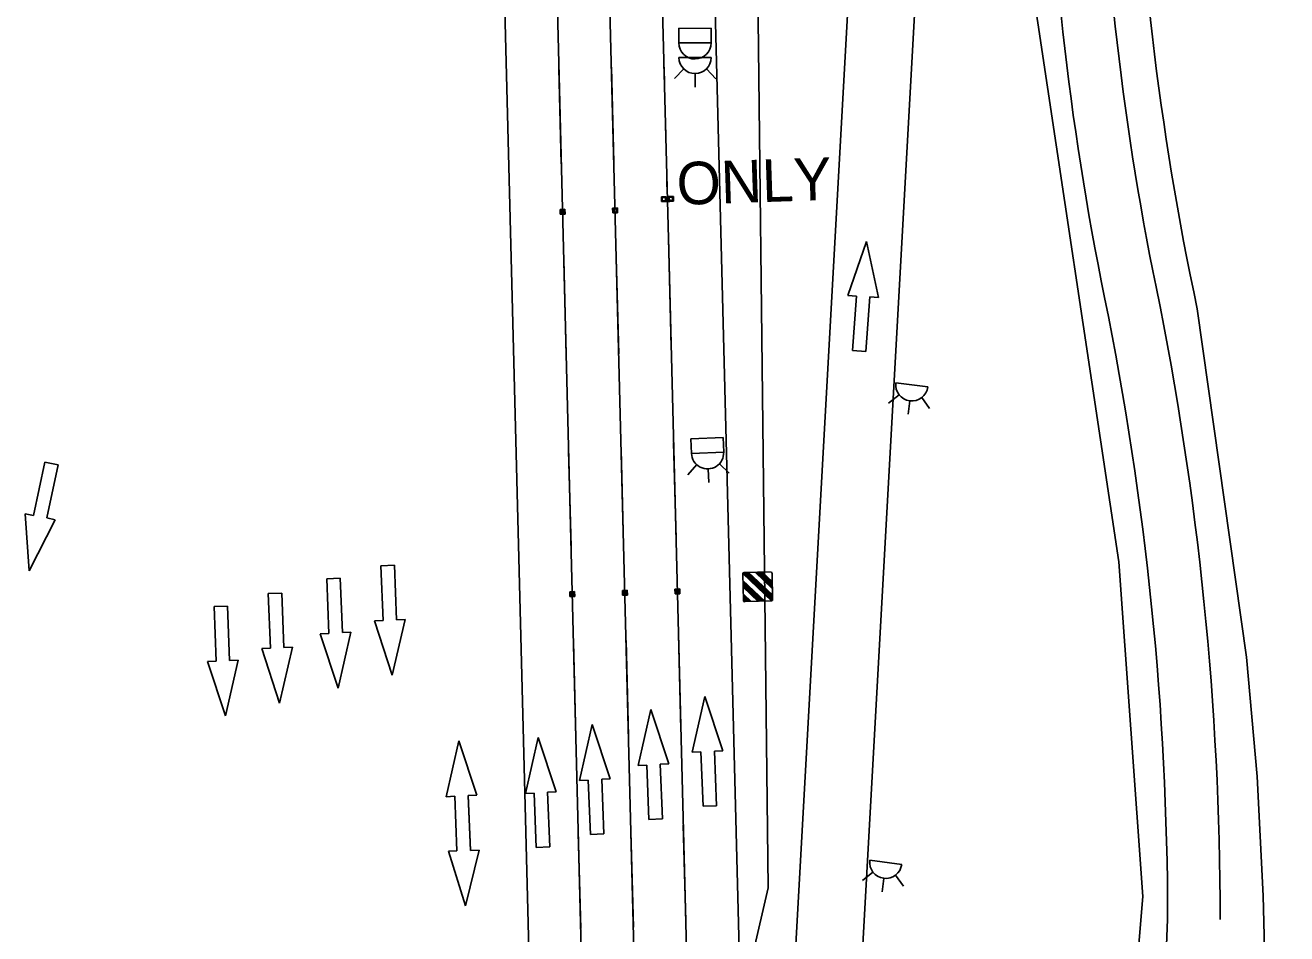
# Model space of a CAD drawing. Extents: x 2471014 to 2497726, y 6959577 to 6980268.
# Drawn here: x 2488453.1 to 2488716.9, y 6961822 to 6962012 of the extents above; entities that cross this region are included whole.
import ezdxf

# ---------------------------------------------------------------- set-up
doc = ezdxf.new("R2010")
doc.units = 0
for name, color, linetype in [('13', 7, 'Continuous'), ('18', 7, 'Continuous'), ('23', 7, 'Continuous'), ('59', 7, 'Continuous'), ('ALIGN_ML_IH35_NB_SB', 7, 'Continuous'), ('C-COMM-STRC', 7, 'Continuous'), ('Level 30', 7, 'Continuous'), ('Level 40', 7, 'Continuous'), ('p_structure fence', 7, 'Continuous'), ('RDW_EOT_35_CD', 7, 'Continuous'), ('RDWY_ALIGN_GP', 7, 'Continuous'), ('RDWY_PAVE_XSTREET_FOC', 7, 'Continuous'), ('S-BRDG-DECK', 7, 'Continuous'), ('V7_25', 7, 'Continuous'), ('V7_50', 7, 'Continuous')]:
    doc.layers.add(name, color=color, linetype=linetype)

msp = doc.modelspace()

# ---------------------------------------------------------------- linework, layer by layer
at = {"layer": '13'}
for p, q in [((2488544.08, 6962379.72), (2488575.08, 6961163.02)), ((2488613.41, 6961804.76), (2488630.42, 6962111.35)), ((2488683.27, 6961604.88), (2488692.01, 6961824.92))]:
    msp.add_line(p, q, dxfattribs=at)
for centre, radius, start, end in [((2489283.89, 6962078.36), 617.5, 181.08448, 191.51692), ((2488036.8, 6961824.25), 655.22, 0.05892, 11.51692)]:
    msp.add_arc(centre, radius, start, end, dxfattribs=at)
at = {"layer": '18'}
for p, q in [((2488588.07, 6962380.84), (2488602.73, 6961805.44)), ((2488616.31, 6961604.28), (2488644.4, 6962110.57))]:
    msp.add_line(p, q, dxfattribs=at)
msp.add_lwpolyline([(2488712.7, 6961791.89), (2488712.61, 6961804.88), (2488712.01, 6961829.87), (2488710.72, 6961854.85), (2488708.49, 6961879.81), (2488698.22, 6961952.71)], dxfattribs=at)
msp.add_arc((2489283.89, 6962078.36), 599, 181.08448, 192.10829, dxfattribs=at)
at = {"layer": '23'}
for p, q in [((2488587.14, 6961976.14), (2488586.13, 6961976.12)), ((2488586.15, 6961975.1), (2488586.13, 6961976.12)), ((2488586.13, 6961976.12), (2488586.29, 6961975.95)), ((2488586.31, 6961975.27), (2488586.15, 6961975.1)), ((2488586.15, 6961975.1), (2488586.42, 6961975.11)), ((2488586.29, 6961975.95), (2488586.43, 6961975.95)), ((2488586.99, 6961975.29), (2488586.31, 6961975.27)), ((2488586.42, 6961975.11), (2488587.17, 6961975.13)), ((2488586.43, 6961975.95), (2488586.97, 6961975.97)), ((2488586.97, 6961975.97), (2488587.14, 6961976.14)), ((2488587.17, 6961975.13), (2488586.99, 6961975.29)), ((2488587.14, 6961976.14), (2488587.17, 6961975.13)), ((2488588.64, 6961976.18), (2488587.63, 6961976.15)), ((2488587.65, 6961975.14), (2488587.63, 6961976.15)), ((2488587.63, 6961976.15), (2488587.79, 6961975.99)), ((2488587.81, 6961975.31), (2488587.65, 6961975.14)), ((2488587.65, 6961975.14), (2488587.92, 6961975.15)), ((2488587.79, 6961975.99), (2488587.93, 6961975.99)), ((2488588.49, 6961975.33), (2488587.81, 6961975.31)), ((2488587.92, 6961975.15), (2488588.67, 6961975.17)), ((2488587.93, 6961975.99), (2488588.47, 6961976.01)), ((2488588.47, 6961976.01), (2488588.64, 6961976.18)), ((2488588.67, 6961975.17), (2488588.49, 6961975.33)), ((2488588.64, 6961976.18), (2488588.67, 6961975.17)), ((2488565.95, 6961973.5), (2488564.94, 6961973.47)), ((2488564.96, 6961972.46), (2488564.94, 6961973.47)), ((2488564.94, 6961973.47), (2488565.1, 6961973.31)), ((2488565.12, 6961972.63), (2488564.96, 6961972.46)), ((2488564.96, 6961972.46), (2488565.23, 6961972.47)), ((2488565.1, 6961973.31), (2488565.24, 6961973.31)), ((2488565.8, 6961972.65), (2488565.12, 6961972.63)), ((2488565.23, 6961972.47), (2488565.98, 6961972.48)), ((2488565.24, 6961973.31), (2488565.78, 6961973.32)), ((2488565.78, 6961973.32), (2488565.95, 6961973.5)), ((2488565.98, 6961972.48), (2488565.8, 6961972.65)), ((2488565.95, 6961973.5), (2488565.98, 6961972.48)), ((2488576.95, 6961973.78), (2488575.93, 6961973.75)), ((2488575.96, 6961972.74), (2488575.93, 6961973.75)), ((2488575.93, 6961973.75), (2488576.1, 6961973.59)), ((2488576.12, 6961972.91), (2488575.96, 6961972.74)), ((2488575.96, 6961972.74), (2488576.23, 6961972.75)), ((2488576.1, 6961973.59), (2488576.24, 6961973.59)), ((2488576.79, 6961972.93), (2488576.12, 6961972.91)), ((2488576.23, 6961972.75), (2488576.97, 6961972.76)), ((2488576.24, 6961973.59), (2488576.78, 6961973.6)), ((2488576.78, 6961973.6), (2488576.95, 6961973.78)), ((2488576.97, 6961972.76), (2488576.79, 6961972.93)), ((2488576.95, 6961973.78), (2488576.97, 6961972.76)), ((2488567.99, 6961893.52), (2488566.98, 6961893.5)), ((2488567, 6961892.48), (2488566.98, 6961893.5)), ((2488566.98, 6961893.5), (2488567.14, 6961893.33)), ((2488567.16, 6961892.66), (2488567, 6961892.48)), ((2488567, 6961892.48), (2488567.27, 6961892.49)), ((2488567.14, 6961893.33), (2488567.28, 6961893.34)), ((2488567.83, 6961892.67), (2488567.16, 6961892.66)), ((2488567.27, 6961892.49), (2488568.02, 6961892.51)), ((2488567.28, 6961893.34), (2488567.82, 6961893.35)), ((2488567.82, 6961893.35), (2488567.99, 6961893.52)), ((2488568.02, 6961892.51), (2488567.83, 6961892.67)), ((2488567.99, 6961893.52), (2488568.02, 6961892.51)), ((2488578.99, 6961893.8), (2488577.97, 6961893.78)), ((2488578, 6961892.76), (2488577.97, 6961893.78)), ((2488577.97, 6961893.78), (2488578.14, 6961893.61)), ((2488578.15, 6961892.94), (2488578, 6961892.76)), ((2488578, 6961892.76), (2488578.27, 6961892.77)), ((2488578.14, 6961893.61), (2488578.28, 6961893.62)), ((2488578.83, 6961892.95), (2488578.15, 6961892.94)), ((2488578.27, 6961892.77), (2488579.01, 6961892.79)), ((2488578.28, 6961893.62), (2488578.81, 6961893.63)), ((2488578.81, 6961893.63), (2488578.99, 6961893.8)), ((2488579.01, 6961892.79), (2488578.83, 6961892.95)), ((2488578.99, 6961893.8), (2488579.01, 6961892.79)), ((2488589.98, 6961894.08), (2488588.97, 6961894.06)), ((2488588.99, 6961893.05), (2488588.97, 6961894.06)), ((2488588.97, 6961894.06), (2488589.13, 6961893.89)), ((2488589.15, 6961893.22), (2488588.99, 6961893.05)), ((2488588.99, 6961893.05), (2488589.26, 6961893.05)), ((2488589.13, 6961893.89), (2488589.27, 6961893.9)), ((2488589.83, 6961893.23), (2488589.15, 6961893.22)), ((2488589.26, 6961893.05), (2488590.01, 6961893.07)), ((2488589.27, 6961893.9), (2488589.81, 6961893.91)), ((2488589.81, 6961893.91), (2488589.98, 6961894.08)), ((2488590.01, 6961893.07), (2488589.83, 6961893.23)), ((2488589.98, 6961894.08), (2488590.01, 6961893.07))]:
    msp.add_line(p, q, dxfattribs=at)
for points in [[(2488586.31, 6961975.27), (2488586.29, 6961975.95), (2488586.97, 6961975.97), (2488586.99, 6961975.29)], [(2488587.81, 6961975.31), (2488587.79, 6961975.99), (2488588.47, 6961976.01), (2488588.49, 6961975.33)], [(2488565.12, 6961972.63), (2488565.1, 6961973.31), (2488565.78, 6961973.32), (2488565.8, 6961972.65)], [(2488576.12, 6961972.91), (2488576.1, 6961973.59), (2488576.78, 6961973.6), (2488576.79, 6961972.93)], [(2488567.16, 6961892.66), (2488567.14, 6961893.33), (2488567.82, 6961893.35), (2488567.83, 6961892.67)], [(2488578.15, 6961892.94), (2488578.14, 6961893.61), (2488578.81, 6961893.63), (2488578.83, 6961892.95)], [(2488589.15, 6961893.22), (2488589.13, 6961893.89), (2488589.81, 6961893.91), (2488589.83, 6961893.23)]]:
    msp.add_lwpolyline(points, close=True, dxfattribs=at)
at = {"layer": '59'}
msp.add_line((2488587.67, 6961964.64), (2488577.07, 6962380.56), dxfattribs=at)
at = {"layer": 'ALIGN_ML_IH35_NB_SB'}
for p, q in [((2488625.13, 6961955.46), (2488629.06, 6961966.79)), ((2488629.06, 6961966.79), (2488631.54, 6961955.07)), ((2488626.92, 6961955.33), (2488625.13, 6961955.46)), ((2488626.12, 6961943.99), (2488626.92, 6961955.33)), ((2488629.74, 6961955.19), (2488628.93, 6961943.79)), ((2488631.54, 6961955.07), (2488629.74, 6961955.19)), ((2488628.93, 6961943.79), (2488626.12, 6961943.99)), ((2488454.83, 6961909.46), (2488457.2, 6961920.64)), ((2488457.2, 6961920.64), (2488459.96, 6961920.05)), ((2488459.96, 6961920.05), (2488457.6, 6961908.93)), ((2488453.91, 6961897.88), (2488453.07, 6961909.83)), ((2488453.07, 6961909.83), (2488454.83, 6961909.46)), ((2488459.36, 6961908.56), (2488453.91, 6961897.88)), ((2488457.6, 6961908.93), (2488459.36, 6961908.56)), ((2488527.48, 6961898.92), (2488530.3, 6961899.03)), ((2488527.91, 6961887.5), (2488527.48, 6961898.92)), ((2488530.3, 6961899.03), (2488530.73, 6961887.66)), ((2488516.16, 6961896.21), (2488518.97, 6961896.31)), ((2488516.59, 6961884.79), (2488516.16, 6961896.21)), ((2488518.97, 6961896.31), (2488519.4, 6961884.95)), ((2488503.91, 6961893.11), (2488506.73, 6961893.21)), ((2488504.34, 6961881.68), (2488503.91, 6961893.11)), ((2488506.73, 6961893.21), (2488507.15, 6961881.85)), ((2488492.58, 6961890.39), (2488495.4, 6961890.5)), ((2488493.01, 6961878.97), (2488492.58, 6961890.39)), ((2488495.4, 6961890.5), (2488495.83, 6961879.14)), ((2488526.12, 6961887.43), (2488527.91, 6961887.5)), ((2488529.85, 6961876.04), (2488526.12, 6961887.43)), ((2488532.53, 6961887.73), (2488529.85, 6961876.04)), ((2488530.73, 6961887.66), (2488532.53, 6961887.73)), ((2488514.79, 6961884.72), (2488516.59, 6961884.79)), ((2488518.52, 6961873.33), (2488514.79, 6961884.72)), ((2488521.2, 6961885.02), (2488518.52, 6961873.33)), ((2488519.4, 6961884.95), (2488521.2, 6961885.02)), ((2488502.54, 6961881.62), (2488504.34, 6961881.68)), ((2488506.27, 6961870.23), (2488502.54, 6961881.62)), ((2488508.95, 6961881.92), (2488506.27, 6961870.23)), ((2488507.15, 6961881.85), (2488508.95, 6961881.92)), ((2488491.21, 6961878.91), (2488493.01, 6961878.97)), ((2488494.94, 6961867.52), (2488491.21, 6961878.91)), ((2488497.62, 6961879.21), (2488494.94, 6961867.52)), ((2488495.83, 6961879.14), (2488497.62, 6961879.21)), ((2488592.59, 6961859.92), (2488595.24, 6961871.62)), ((2488595.24, 6961871.62), (2488599.01, 6961860.24)), ((2488581.27, 6961857.18), (2488583.92, 6961868.87)), ((2488583.92, 6961868.87), (2488587.68, 6961857.5)), ((2488569.03, 6961854.04), (2488571.68, 6961865.74)), ((2488571.68, 6961865.74), (2488575.44, 6961854.36)), ((2488541.12, 6961850.63), (2488543.77, 6961862.33)), ((2488543.77, 6961862.33), (2488547.54, 6961850.95)), ((2488557.71, 6961851.3), (2488560.36, 6961863)), ((2488560.36, 6961863), (2488564.12, 6961851.62)), ((2488594.39, 6961859.99), (2488592.59, 6961859.92)), ((2488594.85, 6961848.63), (2488594.39, 6961859.99)), ((2488599.01, 6961860.24), (2488597.21, 6961860.17)), ((2488597.21, 6961860.17), (2488597.67, 6961848.75)), ((2488583.07, 6961857.25), (2488581.27, 6961857.18)), ((2488583.53, 6961845.89), (2488583.07, 6961857.25)), ((2488587.68, 6961857.5), (2488585.89, 6961857.42)), ((2488585.89, 6961857.42), (2488586.35, 6961846)), ((2488570.83, 6961854.12), (2488569.03, 6961854.04)), ((2488571.29, 6961842.75), (2488570.83, 6961854.12)), ((2488575.44, 6961854.36), (2488573.65, 6961854.29)), ((2488573.65, 6961854.29), (2488574.11, 6961842.87)), ((2488542.92, 6961850.71), (2488541.12, 6961850.63)), ((2488543.38, 6961839.34), (2488542.92, 6961850.71)), ((2488542.93, 6961850.71), (2488543.38, 6961839.34)), ((2488547.54, 6961850.95), (2488545.74, 6961850.88)), ((2488545.74, 6961850.88), (2488546.2, 6961839.46)), ((2488546.2, 6961839.4), (2488545.74, 6961850.82)), ((2488559.51, 6961851.37), (2488557.71, 6961851.3)), ((2488559.97, 6961840.01), (2488559.51, 6961851.37)), ((2488564.12, 6961851.62), (2488562.33, 6961851.55)), ((2488562.33, 6961851.55), (2488562.79, 6961840.12)), ((2488597.67, 6961848.75), (2488594.85, 6961848.63)), ((2488586.35, 6961846), (2488583.53, 6961845.89)), ((2488574.11, 6961842.87), (2488571.29, 6961842.75)), ((2488543.38, 6961839.34), (2488541.58, 6961839.27)), ((2488541.58, 6961839.27), (2488545.16, 6961827.83)), ((2488545.16, 6961827.83), (2488548, 6961839.47)), ((2488548, 6961839.47), (2488546.2, 6961839.4)), ((2488562.79, 6961840.12), (2488559.97, 6961840.01))]:
    msp.add_line(p, q, dxfattribs=at)
at = {"layer": 'C-COMM-STRC'}
for p, q in [((2488589.78, 6962008.29), (2488596.53, 6962008.32)), ((2488596.53, 6962008.32), (2488589.78, 6962008.29)), ((2488596.55, 6962005.27), (2488589.8, 6962005.23)), ((2488595.57, 6962002.88), (2488597.49, 6962000.82)), ((2488590.8, 6962002.85), (2488588.85, 6962000.83)), ((2488593.19, 6962001.88), (2488593.2, 6961999.06))]:
    msp.add_line(p, q, dxfattribs=at)
msp.add_lwpolyline([(2488589.78, 6962008.29), (2488589.76, 6962011.34), (2488596.51, 6962011.38), (2488596.53, 6962008.32)], close=True, dxfattribs=at)
for centre in [(2488593.15, 6962008.31), (2488593.17, 6962005.25)]:
    msp.add_arc(centre, 3.37, 180.3, 0.3, dxfattribs=at)
at = {"layer": 'Level 30'}
for p, q in [((2488635.17, 6961937.21), (2488641.86, 6961936.35)), ((2488635.85, 6961934.71), (2488633.64, 6961932.96)), ((2488638.09, 6961933.43), (2488637.73, 6961930.64)), ((2488640.58, 6961934.11), (2488642.21, 6961931.82)), ((2488629.72, 6961837.33), (2488636.41, 6961836.47)), ((2488630.39, 6961834.84), (2488628.19, 6961833.09)), ((2488635.13, 6961834.23), (2488636.76, 6961831.94)), ((2488632.63, 6961833.55), (2488632.28, 6961830.76))]:
    msp.add_line(p, q, dxfattribs=at)
for centre in [(2488638.52, 6961936.78), (2488633.06, 6961836.9)]:
    msp.add_arc(centre, 3.37, 172.6843, 352.6843, dxfattribs=at)
at = {"layer": 'Level 40'}
for p, q in [((2488586.75, 6962000.63), (2488586.67, 6962003.63)), ((2488587.06, 6961988.64), (2488586.98, 6961991.63)), ((2488587.36, 6961976.64), (2488587.29, 6961979.64)), ((2488587.67, 6961964.64), (2488587.59, 6961967.64))]:
    msp.add_line(p, q, dxfattribs=at)
at = {"layer": 'RDW_EOT_35_CD'}
for p, q in [((2488603.17, 6961897.3), (2488603.36, 6961897.5)), ((2488603.24, 6961897.37), (2488609.3, 6961891.67)), ((2488603.32, 6961897.46), (2488609.38, 6961891.75)), ((2488603.48, 6961897.49), (2488609.38, 6961891.92)), ((2488603.67, 6961897.49), (2488609.37, 6961892.11)), ((2488603.83, 6961897.5), (2488609.37, 6961892.28)), ((2488604.04, 6961897.5), (2488609.37, 6961892.45)), ((2488604.19, 6961897.5), (2488609.36, 6961892.64)), ((2488604.38, 6961897.51), (2488609.36, 6961892.83)), ((2488605.82, 6961897.55), (2488609.33, 6961894.21)), ((2488605.98, 6961897.55), (2488609.32, 6961894.4)), ((2488606.15, 6961897.56), (2488609.32, 6961894.57)), ((2488606.34, 6961897.56), (2488609.32, 6961894.74)), ((2488606.53, 6961897.56), (2488609.31, 6961894.93)), ((2488606.68, 6961897.57), (2488609.31, 6961895.1)), ((2488606.89, 6961897.57), (2488609.31, 6961895.28)), ((2488607.04, 6961897.58), (2488609.3, 6961895.45)), ((2488607.23, 6961897.58), (2488609.3, 6961895.64)), ((2488603.16, 6961897.29), (2488609.2, 6961891.56)), ((2488603.2, 6961895.85), (2488607.76, 6961891.52)), ((2488607.58, 6961891.51), (2488603.21, 6961895.66)), ((2488607.41, 6961891.51), (2488603.21, 6961895.5)), ((2488607.22, 6961891.51), (2488603.21, 6961895.31)), ((2488607.05, 6961891.5), (2488603.22, 6961895.14)), ((2488606.88, 6961891.5), (2488603.22, 6961894.97)), ((2488606.69, 6961891.49), (2488603.23, 6961894.78)), ((2488606.52, 6961891.49), (2488603.23, 6961894.61)), ((2488606.35, 6961891.48), (2488603.24, 6961894.44)), ((2488604.92, 6961891.46), (2488603.28, 6961893.02)), ((2488604.73, 6961891.46), (2488603.28, 6961892.85)), ((2488604.56, 6961891.45), (2488603.29, 6961892.69)), ((2488604.39, 6961891.45), (2488603.29, 6961892.49)), ((2488604.22, 6961891.44), (2488603.3, 6961892.32)), ((2488604.05, 6961891.44), (2488603.3, 6961892.15)), ((2488603.85, 6961891.43), (2488603.31, 6961891.96)), ((2488603.69, 6961891.43), (2488603.31, 6961891.79)), ((2488603.52, 6961891.43), (2488603.32, 6961891.62))]:
    msp.add_line(p, q, dxfattribs=at)
for points in [[(2488608.98, 6961897.64), (2488603.42, 6961897.5)], [(2488609.39, 6961891.83), (2488609.27, 6961897.4)], [(2488603.17, 6961897.24), (2488603.31, 6961891.67)], [(2488603.57, 6961891.43), (2488609.14, 6961891.57)]]:
    msp.add_lwpolyline(points, dxfattribs=at)
for centre, start, end in [((2488603.43, 6961897.25), 91.4799, 181.4799), ((2488609, 6961897.39), 1.4799, 91.4799), ((2488603.58, 6961891.68), 181.4799, 271.4799), ((2488609.14, 6961891.83), 271.4799, 1.4799)]:
    msp.add_arc(centre, 0.253, start, end, dxfattribs=at)
at = {"layer": 'RDWY_ALIGN_GP'}
for p, q in [((2488592.31, 6961925.48), (2488599.05, 6961925.76)), ((2488592.43, 6961922.43), (2488592.31, 6961925.48)), ((2488599.18, 6961922.7), (2488599.05, 6961925.76)), ((2488599.18, 6961922.7), (2488592.43, 6961922.43)), ((2488593.52, 6961920.09), (2488591.64, 6961917.99)), ((2488593.52, 6961920.09), (2488591.64, 6961917.99)), ((2488591.64, 6961917.99), (2488593.52, 6961920.09)), ((2488595.94, 6961919.19), (2488596.05, 6961916.38)), ((2488598.29, 6961920.28), (2488600.28, 6961918.29))]:
    msp.add_line(p, q, dxfattribs=at)
msp.add_arc((2488595.8, 6961922.57), 3.37, 182.3151, 2.3151, dxfattribs=at)
at = {"layer": 'RDWY_PAVE_XSTREET_FOC'}
for p, q in [((2488565.19, 6961982.98), (2488564.68, 6962002.97)), ((2488576.19, 6961983.26), (2488575.68, 6962003.25)), ((2488587.67, 6961964.64), (2488588.18, 6961944.65)), ((2488566.21, 6961942.99), (2488565.7, 6961962.98)), ((2488577.21, 6961943.27), (2488576.7, 6961963.26)), ((2488588.69, 6961924.66), (2488589.2, 6961904.66)), ((2488567.23, 6961903), (2488566.72, 6961922.99)), ((2488578.23, 6961903.28), (2488577.72, 6961923.27)), ((2488589.71, 6961884.67), (2488590.21, 6961864.68)), ((2488568.25, 6961863.01), (2488567.74, 6961883.01)), ((2488579.25, 6961863.29), (2488578.74, 6961883.29)), ((2488590.72, 6961844.68), (2488591.23, 6961824.69)), ((2488569.27, 6961823.03), (2488568.76, 6961843.02)), ((2488580.27, 6961823.31), (2488579.76, 6961843.3))]:
    msp.add_line(p, q, dxfattribs=at)
at = {"layer": 'S-BRDG-DECK'}
for centre, radius, start, end in [((2489283.89, 6962078.36), 606.5, 181.08448, 191.51692), ((2488036.8, 6961824.25), 666.22, 0.05892, 11.51692)]:
    msp.add_arc(centre, radius, start, end, dxfattribs=at)
at = {"layer": 'V7_25'}
for p, q in [((2488566.07, 6962380.28), (2488597.07, 6961163.64)), ((2488555.08, 6962380), (2488586.08, 6961163.33)), ((2488587.67, 6961964.64), (2488608.07, 6961163.94))]:
    msp.add_line(p, q, dxfattribs=at)
at = {"layer": 'V7_50'}
for points in [[(2488678.56, 6961429.45), (2488676.12, 6961701.4), (2488686.81, 6961829.79), (2488681.81, 6961899.73), (2488663.06, 6962024.65), (2488658.12, 6962106.11), (2488660.52, 6962142.63), (2488663.59, 6962148.19), (2488665.59, 6962148.17), (2488667.89, 6962147.73), (2488668.9, 6962274.3), (2488671.26, 6962295.73), (2488674.47, 6962319.21), (2488677.73, 6962343.9), (2488686.19, 6962346.8), (2488706.86, 6962347.54), (2488716.94, 6962346.72), (2488715.38, 6962456.34)], [(2488606.41, 6962447.22), (2488605.3, 6962104.13), (2488608.48, 6961831.56), (2488602.28, 6961804.75), (2488597.48, 6961803.6), (2488609.69, 6961423.76)]]:
    msp.add_lwpolyline(points, dxfattribs=at)

# ---------------------------------------------------------------- texts
at = {"layer": 'p_structure fence'}
msp.add_text('ONLY', height=8.898, rotation=1.9234, dxfattribs=at).set_placement((2488589.46, 6961974.4))

doc.saveas('drawing.dxf')
